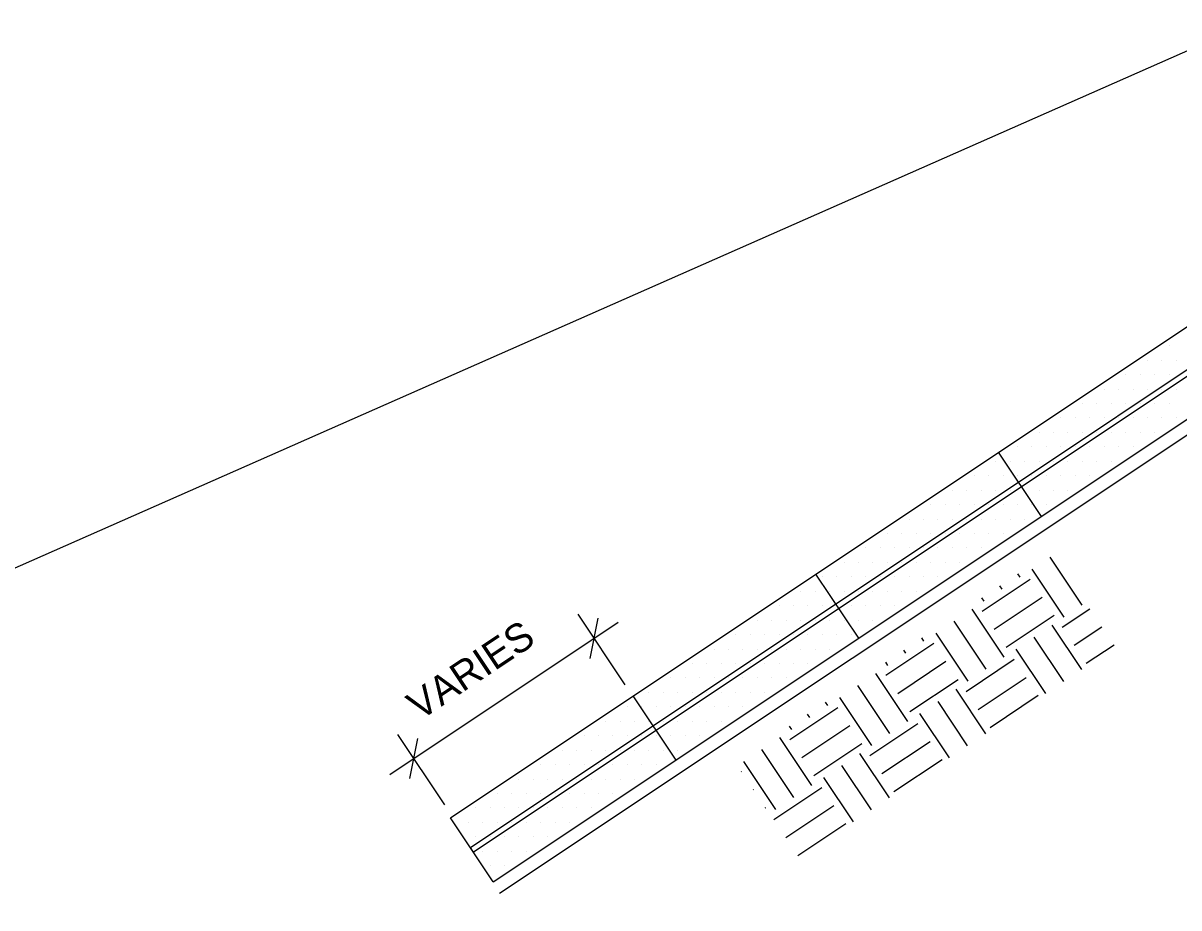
# Model space of a CAD drawing. Extents: x 638850 to 644908, y 297188 to 298900.
# Drawn here: x 641608.6 to 641716.6, y 297466.1 to 297548.8 of the extents above; entities that cross this region are included whole.
import ezdxf

# ---------------------------------------------------------------- set-up
doc = ezdxf.new("R2010")
doc.units = 0
for name, color, linetype in [('1', 7, 'Continuous'), ('12', 7, 'Continuous'), ('13', 7, 'Continuous'), ('3', 7, 'Continuous'), ('4', 7, 'Continuous'), ('5', 7, 'Continuous'), ('6', 7, 'Continuous'), ('8', 7, 'Continuous')]:
    doc.layers.add(name, color=color, linetype=linetype)

msp = doc.modelspace()

# ---------------------------------------------------------------- linework, layer by layer
at = {"layer": '1'}
msp.add_line((644544.42, 298794.06), (640943.9, 297204.77), dxfattribs=at)
at = {"layer": '12'}
for p, q in [((641715.68, 297518.63), (641715.68, 297518.63)), ((641713.66, 297517.28), (641713.66, 297517.28)), ((641715.01, 297517.28), (641715.01, 297517.28)), ((641716.36, 297517.28), (641716.36, 297517.28)), ((641711.63, 297515.93), (641711.63, 297515.93)), ((641712.98, 297515.93), (641712.98, 297515.93)), ((641714.33, 297515.93), (641714.33, 297515.93)), ((641715.68, 297515.93), (641715.68, 297515.93)), ((641709.61, 297514.58), (641709.61, 297514.58)), ((641710.96, 297514.58), (641710.96, 297514.58)), ((641712.31, 297514.58), (641712.31, 297514.58)), ((641713.66, 297514.58), (641713.66, 297514.58)), ((641715.01, 297514.58), (641715.01, 297514.58)), ((641716.36, 297514.58), (641716.36, 297514.58)), ((641707.58, 297513.23), (641707.58, 297513.23)), ((641708.93, 297513.23), (641708.93, 297513.23)), ((641710.28, 297513.23), (641710.28, 297513.23)), ((641711.63, 297513.23), (641711.63, 297513.23)), ((641712.98, 297513.23), (641712.98, 297513.23)), ((641714.33, 297513.23), (641714.33, 297513.23)), ((641715.68, 297513.23), (641715.68, 297513.23)), ((641705.56, 297511.88), (641705.56, 297511.88)), ((641706.91, 297511.88), (641706.91, 297511.88)), ((641708.26, 297511.88), (641708.26, 297511.88)), ((641709.61, 297511.88), (641709.61, 297511.88)), ((641710.96, 297511.88), (641710.96, 297511.88)), ((641712.31, 297511.88), (641712.31, 297511.88)), ((641713.66, 297511.88), (641713.66, 297511.88)), ((641715.01, 297511.88), (641715.01, 297511.88)), ((641716.36, 297511.88), (641716.36, 297511.88)), ((641703.53, 297510.53), (641703.53, 297510.53)), ((641704.88, 297510.53), (641704.88, 297510.53)), ((641706.23, 297510.53), (641706.23, 297510.53)), ((641707.58, 297510.53), (641707.58, 297510.53)), ((641708.93, 297510.53), (641708.93, 297510.53)), ((641710.28, 297510.53), (641710.28, 297510.53)), ((641711.63, 297510.53), (641711.63, 297510.53)), ((641712.98, 297510.53), (641712.98, 297510.53)), ((641714.33, 297510.53), (641714.33, 297510.53)), ((641701.51, 297509.18), (641701.51, 297509.18)), ((641702.86, 297509.18), (641702.86, 297509.18)), ((641704.21, 297509.18), (641704.21, 297509.18)), ((641705.56, 297509.18), (641705.56, 297509.18)), ((641706.91, 297509.18), (641706.91, 297509.18)), ((641708.26, 297509.18), (641708.26, 297509.18)), ((641709.61, 297509.18), (641709.61, 297509.18)), ((641710.96, 297509.18), (641710.96, 297509.18)), ((641712.31, 297509.18), (641712.31, 297509.18)), ((641699.48, 297507.83), (641699.48, 297507.83)), ((641700.83, 297507.83), (641700.83, 297507.83)), ((641702.18, 297507.83), (641702.18, 297507.83)), ((641703.53, 297507.83), (641703.53, 297507.83)), ((641704.88, 297507.83), (641704.88, 297507.83)), ((641706.23, 297507.83), (641706.23, 297507.83)), ((641707.58, 297507.83), (641707.58, 297507.83)), ((641708.93, 297507.83), (641708.93, 297507.83)), ((641710.28, 297507.83), (641710.28, 297507.83)), ((641697.46, 297506.48), (641697.46, 297506.48)), ((641698.81, 297506.48), (641698.81, 297506.48)), ((641700.16, 297506.48), (641700.16, 297506.48)), ((641701.51, 297506.48), (641701.51, 297506.48)), ((641702.86, 297506.48), (641702.86, 297506.48)), ((641704.21, 297506.48), (641704.21, 297506.48)), ((641705.56, 297506.48), (641705.56, 297506.48)), ((641706.91, 297506.48), (641706.91, 297506.48)), ((641708.26, 297506.48), (641708.26, 297506.48)), ((641695.43, 297505.13), (641695.43, 297505.13)), ((641696.78, 297505.13), (641696.78, 297505.13)), ((641698.13, 297505.13), (641698.13, 297505.13)), ((641699.48, 297505.13), (641699.48, 297505.13)), ((641700.83, 297505.13), (641700.83, 297505.13)), ((641702.18, 297505.13), (641702.18, 297505.13)), ((641703.53, 297505.13), (641703.53, 297505.13)), ((641704.88, 297505.13), (641704.88, 297505.13)), ((641706.23, 297505.13), (641706.23, 297505.13)), ((641693.41, 297503.78), (641693.41, 297503.78)), ((641694.76, 297503.78), (641694.76, 297503.78)), ((641696.11, 297503.78), (641696.11, 297503.78)), ((641697.46, 297503.78), (641697.46, 297503.78)), ((641698.81, 297503.78), (641698.81, 297503.78)), ((641700.16, 297503.78), (641700.16, 297503.78)), ((641701.51, 297503.78), (641701.51, 297503.78)), ((641702.86, 297503.78), (641702.86, 297503.78)), ((641704.21, 297503.78), (641704.21, 297503.78)), ((641691.38, 297502.43), (641691.38, 297502.43)), ((641692.73, 297502.43), (641692.73, 297502.43)), ((641694.08, 297502.43), (641694.08, 297502.43)), ((641695.43, 297502.43), (641695.43, 297502.43)), ((641696.78, 297502.43), (641696.78, 297502.43)), ((641698.13, 297502.43), (641698.13, 297502.43)), ((641699.48, 297502.43), (641699.48, 297502.43)), ((641700.83, 297502.43), (641700.83, 297502.43)), ((641702.18, 297502.43), (641702.18, 297502.43)), ((641689.36, 297501.08), (641689.36, 297501.08)), ((641690.71, 297501.08), (641690.71, 297501.08)), ((641692.06, 297501.08), (641692.06, 297501.08)), ((641693.41, 297501.08), (641693.41, 297501.08)), ((641694.76, 297501.08), (641694.76, 297501.08)), ((641696.11, 297501.08), (641696.11, 297501.08)), ((641697.46, 297501.08), (641697.46, 297501.08)), ((641698.81, 297501.08), (641698.81, 297501.08)), ((641700.16, 297501.08), (641700.16, 297501.08)), ((641687.33, 297499.73), (641687.33, 297499.73)), ((641688.68, 297499.73), (641688.68, 297499.73)), ((641690.03, 297499.73), (641690.03, 297499.73)), ((641691.38, 297499.73), (641691.38, 297499.73)), ((641692.73, 297499.73), (641692.73, 297499.73)), ((641694.08, 297499.73), (641694.08, 297499.73)), ((641695.43, 297499.73), (641695.43, 297499.73)), ((641696.78, 297499.73), (641696.78, 297499.73)), ((641698.13, 297499.73), (641698.13, 297499.73)), ((641685.31, 297498.38), (641685.31, 297498.38)), ((641686.66, 297498.38), (641686.66, 297498.38)), ((641688.01, 297498.38), (641688.01, 297498.38)), ((641689.36, 297498.38), (641689.36, 297498.38)), ((641690.71, 297498.38), (641690.71, 297498.38)), ((641692.06, 297498.38), (641692.06, 297498.38)), ((641693.41, 297498.38), (641693.41, 297498.38)), ((641694.76, 297498.38), (641694.76, 297498.38)), ((641696.11, 297498.38), (641696.11, 297498.38)), ((641683.28, 297497.03), (641683.28, 297497.03)), ((641684.63, 297497.03), (641684.63, 297497.03)), ((641685.98, 297497.03), (641685.98, 297497.03)), ((641687.33, 297497.03), (641687.33, 297497.03)), ((641688.68, 297497.03), (641688.68, 297497.03)), ((641690.03, 297497.03), (641690.03, 297497.03)), ((641691.38, 297497.03), (641691.38, 297497.03)), ((641692.73, 297497.03), (641692.73, 297497.03)), ((641694.08, 297497.03), (641694.08, 297497.03)), ((641681.26, 297495.68), (641681.26, 297495.68)), ((641682.61, 297495.68), (641682.61, 297495.68)), ((641683.96, 297495.68), (641683.96, 297495.68)), ((641685.31, 297495.68), (641685.31, 297495.68)), ((641686.66, 297495.68), (641686.66, 297495.68)), ((641688.01, 297495.68), (641688.01, 297495.68)), ((641689.36, 297495.68), (641689.36, 297495.68)), ((641690.71, 297495.68), (641690.71, 297495.68)), ((641692.06, 297495.68), (641692.06, 297495.68)), ((641679.23, 297494.33), (641679.23, 297494.33)), ((641680.58, 297494.33), (641680.58, 297494.33)), ((641681.93, 297494.33), (641681.93, 297494.33)), ((641683.28, 297494.33), (641683.28, 297494.33)), ((641684.63, 297494.33), (641684.63, 297494.33)), ((641685.98, 297494.33), (641685.98, 297494.33)), ((641687.33, 297494.33), (641687.33, 297494.33)), ((641688.68, 297494.33), (641688.68, 297494.33)), ((641690.03, 297494.33), (641690.03, 297494.33)), ((641677.21, 297492.98), (641677.21, 297492.98)), ((641678.56, 297492.98), (641678.56, 297492.98)), ((641679.91, 297492.98), (641679.91, 297492.98)), ((641681.26, 297492.98), (641681.26, 297492.98)), ((641682.61, 297492.98), (641682.61, 297492.98)), ((641683.96, 297492.98), (641683.96, 297492.98)), ((641685.31, 297492.98), (641685.31, 297492.98)), ((641686.66, 297492.98), (641686.66, 297492.98)), ((641688.01, 297492.98), (641688.01, 297492.98)), ((641675.18, 297491.63), (641675.18, 297491.63)), ((641676.53, 297491.63), (641676.53, 297491.63)), ((641677.88, 297491.63), (641677.88, 297491.63)), ((641679.23, 297491.63), (641679.23, 297491.63)), ((641680.58, 297491.63), (641680.58, 297491.63)), ((641681.93, 297491.63), (641681.93, 297491.63)), ((641683.28, 297491.63), (641683.28, 297491.63)), ((641684.63, 297491.63), (641684.63, 297491.63)), ((641685.98, 297491.63), (641685.98, 297491.63)), ((641673.16, 297490.28), (641673.16, 297490.28)), ((641674.51, 297490.28), (641674.51, 297490.28)), ((641675.86, 297490.28), (641675.86, 297490.28)), ((641677.21, 297490.28), (641677.21, 297490.28)), ((641678.56, 297490.28), (641678.56, 297490.28)), ((641679.91, 297490.28), (641679.91, 297490.28)), ((641681.26, 297490.28), (641681.26, 297490.28)), ((641682.61, 297490.28), (641682.61, 297490.28)), ((641683.96, 297490.28), (641683.96, 297490.28)), ((641671.13, 297488.93), (641671.13, 297488.93)), ((641672.48, 297488.93), (641672.48, 297488.93)), ((641673.83, 297488.93), (641673.83, 297488.93)), ((641675.18, 297488.93), (641675.18, 297488.93)), ((641676.53, 297488.93), (641676.53, 297488.93)), ((641677.88, 297488.93), (641677.88, 297488.93)), ((641679.23, 297488.93), (641679.23, 297488.93)), ((641680.58, 297488.93), (641680.58, 297488.93)), ((641681.93, 297488.93), (641681.93, 297488.93)), ((641669.11, 297487.58), (641669.11, 297487.58)), ((641670.46, 297487.58), (641670.46, 297487.58)), ((641671.81, 297487.58), (641671.81, 297487.58)), ((641673.16, 297487.58), (641673.16, 297487.58)), ((641674.51, 297487.58), (641674.51, 297487.58)), ((641675.86, 297487.58), (641675.86, 297487.58)), ((641677.21, 297487.58), (641677.21, 297487.58)), ((641678.56, 297487.58), (641678.56, 297487.58)), ((641679.91, 297487.58), (641679.91, 297487.58)), ((641667.08, 297486.23), (641667.08, 297486.23)), ((641668.43, 297486.23), (641668.43, 297486.23)), ((641669.78, 297486.23), (641669.78, 297486.23)), ((641671.13, 297486.23), (641671.13, 297486.23)), ((641672.48, 297486.23), (641672.48, 297486.23)), ((641673.83, 297486.23), (641673.83, 297486.23)), ((641675.18, 297486.23), (641675.18, 297486.23)), ((641676.53, 297486.23), (641676.53, 297486.23)), ((641677.88, 297486.23), (641677.88, 297486.23)), ((641665.06, 297484.88), (641665.06, 297484.88)), ((641666.41, 297484.88), (641666.41, 297484.88)), ((641667.76, 297484.88), (641667.76, 297484.88)), ((641669.11, 297484.88), (641669.11, 297484.88)), ((641670.46, 297484.88), (641670.46, 297484.88)), ((641671.81, 297484.88), (641671.81, 297484.88)), ((641673.16, 297484.88), (641673.16, 297484.88)), ((641674.51, 297484.88), (641674.51, 297484.88)), ((641675.86, 297484.88), (641675.86, 297484.88)), ((641663.03, 297483.53), (641663.03, 297483.53)), ((641664.38, 297483.53), (641664.38, 297483.53)), ((641665.73, 297483.53), (641665.73, 297483.53)), ((641667.08, 297483.53), (641667.08, 297483.53)), ((641668.43, 297483.53), (641668.43, 297483.53)), ((641669.78, 297483.53), (641669.78, 297483.53)), ((641671.13, 297483.53), (641671.13, 297483.53)), ((641672.48, 297483.53), (641672.48, 297483.53)), ((641673.83, 297483.53), (641673.83, 297483.53)), ((641661.01, 297482.18), (641661.01, 297482.18)), ((641662.36, 297482.18), (641662.36, 297482.18)), ((641663.71, 297482.18), (641663.71, 297482.18)), ((641665.06, 297482.18), (641665.06, 297482.18)), ((641666.41, 297482.18), (641666.41, 297482.18)), ((641667.76, 297482.18), (641667.76, 297482.18)), ((641669.11, 297482.18), (641669.11, 297482.18)), ((641670.46, 297482.18), (641670.46, 297482.18)), ((641671.81, 297482.18), (641671.81, 297482.18)), ((641658.98, 297480.83), (641658.98, 297480.83)), ((641660.33, 297480.83), (641660.33, 297480.83)), ((641661.68, 297480.83), (641661.68, 297480.83)), ((641663.03, 297480.83), (641663.03, 297480.83)), ((641664.38, 297480.83), (641664.38, 297480.83)), ((641665.73, 297480.83), (641665.73, 297480.83)), ((641667.08, 297480.83), (641667.08, 297480.83)), ((641668.43, 297480.83), (641668.43, 297480.83)), ((641669.78, 297480.83), (641669.78, 297480.83)), ((641656.96, 297479.48), (641656.96, 297479.48)), ((641658.31, 297479.48), (641658.31, 297479.48)), ((641659.66, 297479.48), (641659.66, 297479.48)), ((641661.01, 297479.48), (641661.01, 297479.48)), ((641662.36, 297479.48), (641662.36, 297479.48)), ((641663.71, 297479.48), (641663.71, 297479.48)), ((641665.06, 297479.48), (641665.06, 297479.48)), ((641666.41, 297479.48), (641666.41, 297479.48)), ((641667.76, 297479.48), (641667.76, 297479.48)), ((641654.93, 297478.13), (641654.93, 297478.13)), ((641656.28, 297478.13), (641656.28, 297478.13)), ((641657.63, 297478.13), (641657.63, 297478.13)), ((641658.98, 297478.13), (641658.98, 297478.13)), ((641660.33, 297478.13), (641660.33, 297478.13)), ((641661.68, 297478.13), (641661.68, 297478.13)), ((641663.03, 297478.13), (641663.03, 297478.13)), ((641664.38, 297478.13), (641664.38, 297478.13)), ((641665.73, 297478.13), (641665.73, 297478.13)), ((641652.91, 297476.78), (641652.91, 297476.78)), ((641654.26, 297476.78), (641654.26, 297476.78)), ((641655.61, 297476.78), (641655.61, 297476.78)), ((641656.96, 297476.78), (641656.96, 297476.78)), ((641658.31, 297476.78), (641658.31, 297476.78)), ((641659.66, 297476.78), (641659.66, 297476.78)), ((641661.01, 297476.78), (641661.01, 297476.78)), ((641662.36, 297476.78), (641662.36, 297476.78)), ((641663.71, 297476.78), (641663.71, 297476.78)), ((641650.88, 297475.43), (641650.88, 297475.43)), ((641652.23, 297475.43), (641652.23, 297475.43)), ((641653.58, 297475.43), (641653.58, 297475.43)), ((641654.93, 297475.43), (641654.93, 297475.43)), ((641656.28, 297475.43), (641656.28, 297475.43)), ((641657.63, 297475.43), (641657.63, 297475.43)), ((641658.98, 297475.43), (641658.98, 297475.43)), ((641660.33, 297475.43), (641660.33, 297475.43)), ((641661.68, 297475.43), (641661.68, 297475.43)), ((641648.86, 297474.08), (641648.86, 297474.08)), ((641650.21, 297474.08), (641650.21, 297474.08)), ((641651.56, 297474.08), (641651.56, 297474.08)), ((641652.91, 297474.08), (641652.91, 297474.08)), ((641654.26, 297474.08), (641654.26, 297474.08)), ((641655.61, 297474.08), (641655.61, 297474.08)), ((641656.96, 297474.08), (641656.96, 297474.08)), ((641658.31, 297474.08), (641658.31, 297474.08)), ((641659.66, 297474.08), (641659.66, 297474.08)), ((641650.88, 297472.73), (641650.88, 297472.73)), ((641652.23, 297472.73), (641652.23, 297472.73)), ((641653.58, 297472.73), (641653.58, 297472.73)), ((641654.93, 297472.73), (641654.93, 297472.73)), ((641656.28, 297472.73), (641656.28, 297472.73)), ((641657.63, 297472.73), (641657.63, 297472.73)), ((641651.56, 297471.38), (641651.56, 297471.38)), ((641652.91, 297471.38), (641652.91, 297471.38)), ((641654.26, 297471.38), (641654.26, 297471.38)), ((641655.61, 297471.38), (641655.61, 297471.38)), ((641652.23, 297470.03), (641652.23, 297470.03)), ((641653.58, 297470.03), (641653.58, 297470.03))]:
    msp.add_line(p, q, dxfattribs=at)
at = {"layer": '13'}
for p, q in [((641707.56, 297494.38), (641704.57, 297498.87)), ((641705.88, 297493.26), (641702.88, 297497.75)), ((641698.2, 297493.82), (641702.7, 297496.81)), ((641701.76, 297497), (641701.55, 297497.31)), ((641700.07, 297495.88), (641699.87, 297496.19)), ((641698.39, 297494.76), (641698.18, 297495.06)), ((641699.33, 297492.13), (641703.82, 297495.13)), ((641700.26, 297489.51), (641697.27, 297494.01)), ((641700.45, 297490.45), (641704.94, 297493.44)), ((641705.69, 297492.32), (641708.28, 297494.05)), ((641698.58, 297488.39), (641695.58, 297492.88)), ((641707.52, 297488.36), (641704.75, 297492.51)), ((641706.82, 297490.64), (641709.4, 297492.36)), ((641692.77, 297491.01), (641692.57, 297491.32)), ((641696.89, 297487.27), (641693.9, 297491.76)), ((641705.84, 297487.24), (641703.07, 297491.39)), ((641689.22, 297487.83), (641693.71, 297490.82)), ((641691.09, 297489.89), (641690.88, 297490.19)), ((641704.15, 297486.12), (641701.39, 297490.26)), ((641707.94, 297488.95), (641710.53, 297490.68)), ((641689.41, 297488.76), (641689.2, 297489.07)), ((641690.34, 297486.14), (641694.83, 297489.14)), ((641696.71, 297486.33), (641701.2, 297489.33)), ((641691.28, 297483.52), (641688.28, 297488.01)), ((641689.59, 297482.4), (641686.6, 297486.89)), ((641691.46, 297484.46), (641695.96, 297487.45)), ((641697.83, 297484.64), (641702.32, 297487.64)), ((641687.91, 297481.27), (641684.91, 297485.77)), ((641698.54, 297482.37), (641695.77, 297486.52)), ((641698.95, 297482.96), (641703.45, 297485.96)), ((641680.23, 297481.83), (641684.73, 297484.83)), ((641683.79, 297485.02), (641683.58, 297485.33)), ((641696.85, 297481.25), (641694.09, 297485.39)), ((641682.1, 297483.89), (641681.9, 297484.2)), ((641695.17, 297480.12), (641692.4, 297484.27)), ((641680.42, 297482.77), (641680.21, 297483.08)), ((641681.36, 297480.15), (641685.85, 297483.15)), ((641687.72, 297480.34), (641692.21, 297483.33)), ((641682.29, 297477.53), (641679.3, 297482.02)), ((641682.48, 297478.47), (641686.97, 297481.46)), ((641688.84, 297478.65), (641693.34, 297481.65)), ((641680.61, 297476.4), (641677.61, 297480.9)), ((641689.55, 297476.38), (641686.79, 297480.53)), ((641678.92, 297475.28), (641675.93, 297479.77)), ((641687.87, 297475.26), (641685.1, 297479.4)), ((641689.97, 297476.97), (641694.46, 297479.96)), ((641675.7, 297478.81), (641675.74, 297478.84)), ((641686.18, 297474.13), (641683.42, 297478.28)), ((641676.82, 297477.13), (641676.86, 297477.15)), ((641678.74, 297474.35), (641683.23, 297477.34)), ((641677.95, 297475.44), (641677.99, 297475.47)), ((641679.86, 297472.66), (641684.35, 297475.66)), ((641680.98, 297470.98), (641685.48, 297473.97))]:
    msp.add_line(p, q, dxfattribs=at)
at = {"layer": '4'}
msp.add_lwpolyline([(641650.39, 297471.74), (641771.27, 297552.37), (641771.57, 297551.92), (641650.69, 297471.29)], close=True, dxfattribs=at)
at = {"layer": '5'}
for p, q in [((641648.54, 297474.51), (641768.04, 297554.21)), ((641652.53, 297468.52), (641772.03, 297548.22)), ((641703.75, 297502.68), (641699.75, 297508.67)), ((641686.68, 297491.29), (641682.68, 297497.28)), ((641669.61, 297479.91), (641665.61, 297485.9)), ((641652.53, 297468.52), (641648.54, 297474.51))]:
    msp.add_line(p, q, dxfattribs=at)
at = {"layer": '6'}
for p, q in [((641664.84, 297486.94), (641660.45, 297493.53)), ((641661.57, 297489.41), (641662.32, 297493.16)), ((641642.87, 297478.56), (641664.19, 297492.79)), ((641661.95, 297491.29), (641661.95, 297491.29)), ((641648.01, 297475.72), (641643.62, 297482.31)), ((641644.74, 297478.19), (641645.49, 297481.93))]:
    msp.add_line(p, q, dxfattribs=at)
at = {"layer": '8'}
msp.add_line((641653.12, 297467.47), (641773.63, 297547.84), dxfattribs=at)

# ---------------------------------------------------------------- texts
at = {"layer": '3'}
msp.add_text('VARIES', height=2.689, rotation=33.7, dxfattribs=at).set_placement((641645.67, 297483.55))

doc.saveas('drawing.dxf')
